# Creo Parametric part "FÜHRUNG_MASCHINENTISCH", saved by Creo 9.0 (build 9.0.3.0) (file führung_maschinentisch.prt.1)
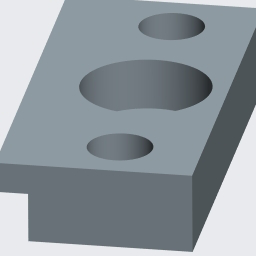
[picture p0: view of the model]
Units: millimeter Kilogram Sec (mmKs); MM, KILOGRAM, SECS
Materials in the file: STAHL

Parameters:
  WERKSTOFF = "Stahl"
  ERSTELLER = "ARINDA"
  BENENNUNG = "XXX"
  TEILETYP = "K"
  PTC_MASTER_MATERIAL = "STAHL"
  SCHRAUBEN_GROESSE = "M4x.7"
  METRISCH = "JA"

Other parameters: MASSE, ANSENKDURCHMESSER, ANSENKTIEFE, BOHR_DURCHM

Created from: ARINDA_STARTTEIL.PRT

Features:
  1. coordinate system
  2. datum plane "RECHTS_Y-Z"
  3. datum plane "OBEN_X-Z"
  4. datum plane "VORNE_X-Y"
  5. datum axis
  6. datum axis
  7. datum axis
  8. datum point "PNT0"
  9. extrusion "Profil 1"
  10. hole "Bohrung 1"
  11. sketch "Skizze 1"
  12. pattern "Muster 1"
  13. hole "Bohrung 2"
  14. hole "Bohrung 2 [9]"

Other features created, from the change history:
  coordinate system "CS1"

Other named items: GRUNDKÖRPER, BEFESTIGUNG, VERSTIFTUNG, STIFTLOCH, A_X, A_Y, A_Z, CS0

Layers: 01_ACHSEN, 01_ACHSEN_STD, 01_EBENEN_STD, 01_KOORDSYS_STD, 01_KURVEN, 01_PUNKTE_STD, VOLUMENGEOMETRIE

Notes: M4x.7 | LÖSCHEN |  BOHREN (  | 4.500 | DURCH |   -(  |  ) BOHRUNG

Surfaces: 9 plane, 6 cylinder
